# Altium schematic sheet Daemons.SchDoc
size B; DocumentNumber: 1; SheetNumber: 1; SheetTotal: 1
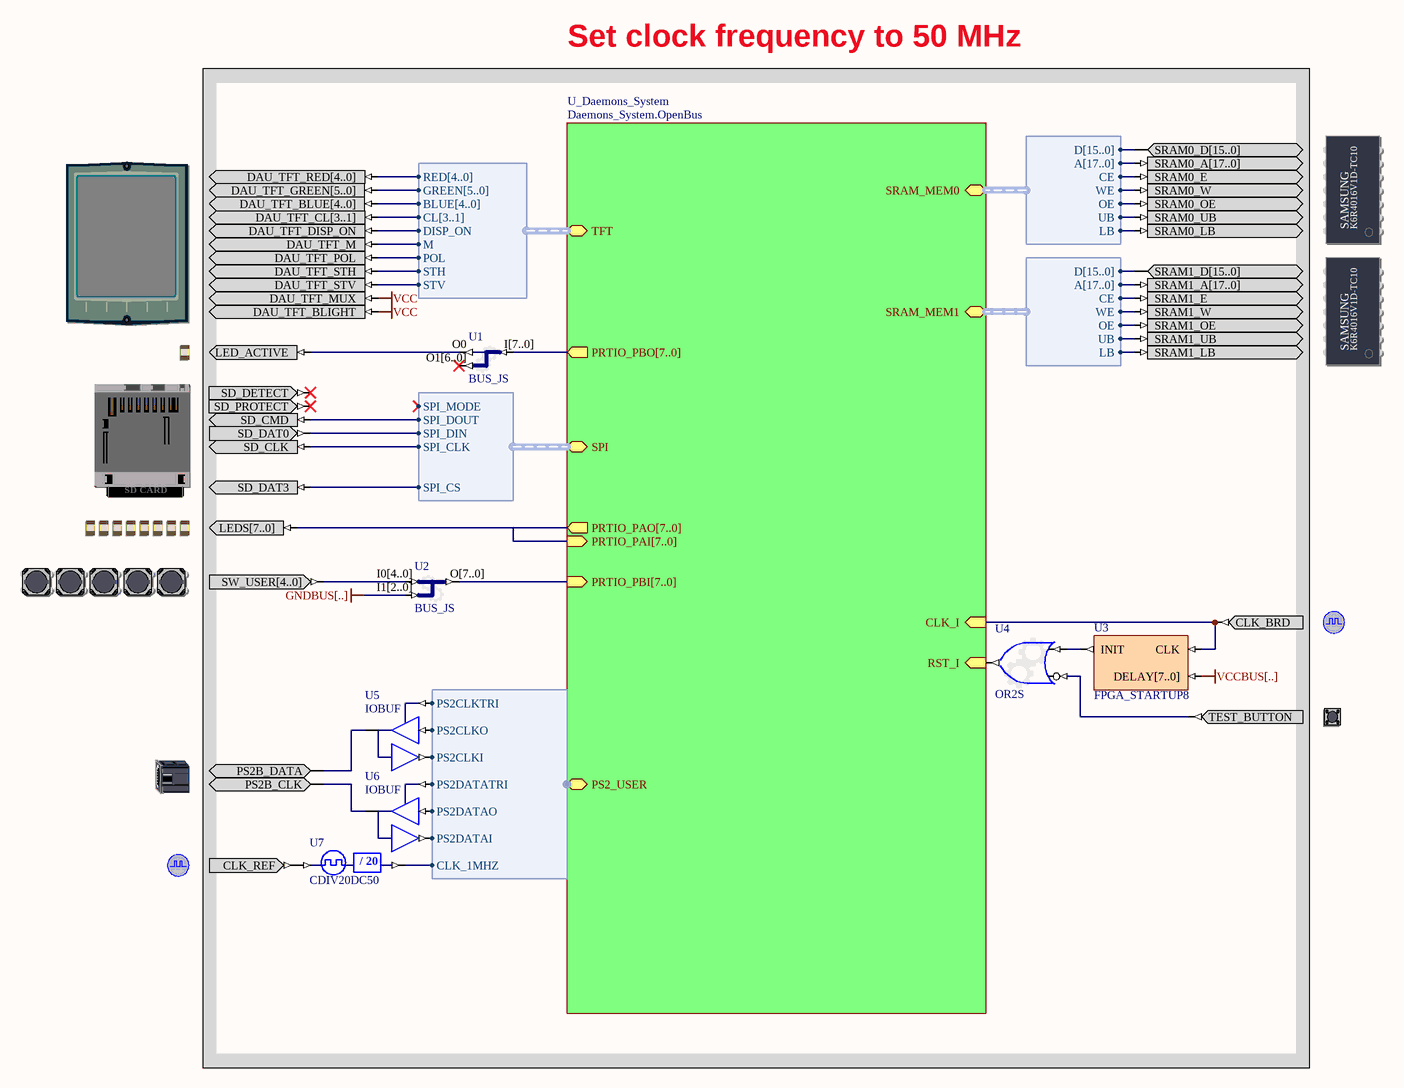
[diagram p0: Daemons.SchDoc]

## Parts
(Parts that share a designator on the sheet are numbered #1, #2 ... from top to bottom, then left to right.)
?#1  SRAM_DAUGHTER0  (value not drawn)
?#2  TFT_LCD  (value not drawn)
?#3  SRAM_DAUGHTER1  (value not drawn)
?#4  LED_ACTIVE  (value not drawn)
?#5  SD_CARD  (value not drawn)
?#6  LED  (value not drawn)
?#7  USER_BUTTONS  (value not drawn)
?#8  CLOCK_BOARD  (value not drawn)
?#9  TEST_BUTTON  (value not drawn)
?#10  PS2B  (value not drawn)
?#11  CLOCK_REFERENCE  (value not drawn)
U1  BUS_JS
U2  BUS_JS
U3  FPGA_STARTUP8
U4  OR2S
U5  IOBUF
U6  IOBUF
U7  CDIV20DC50

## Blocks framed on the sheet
Set clock frequency to 50 MHz: ?#1-?#11 U1-U7

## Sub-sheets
U_Daemons_System = Daemons_System.OpenBus: CLK_I (in), RST_I (in), PRTIO_PAO[7..0] (out), PRTIO_PAI[7..0] (in), PRTIO_PBO[7..0] (out), PRTIO_PBI[7..0] (in), TFT (harness VGA32_TFT), SPI (harness SPI_W), PS2_USER (harness PS2_W), SRAM_MEM0 (harness WB_MEM_CTRL_SRAM16_A18), SRAM_MEM1 (harness WB_MEM_CTRL_SRAM16_A18)

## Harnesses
VGA32_TFT: RED[4..0], GREEN[5..0], BLUE[4..0], CL[3..1], DISP_ON, M, POL, STH, STV
SPI_W: SPI_DOUT, SPI_DIN, SPI_CLK, SPI_MODE, SPI_CS
PS2_W: PS2CLKTRI, PS2CLKO, PS2CLKI, PS2DATATRI, PS2DATAO, PS2DATAI, CLK_1MHZ
WB_MEM_CTRL_SRAM16_A18: D[15..0], A[17..0], CE, WE, OE, UB, LB

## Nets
VCC: ?#2.DAU_TFT_BLIGHT ?#2.DAU_TFT_MUX
VCCBUS[..]: U3.DELAY[7..0]
Net?#1_SRAM0_E: ?#1.SRAM0_E ; sheet U_Daemons_System/SRAM_MEM0.CE
Net?#1_SRAM0_LB: ?#1.SRAM0_LB ; sheet U_Daemons_System/SRAM_MEM0.LB
Net?#1_SRAM0_OE: ?#1.SRAM0_OE ; sheet U_Daemons_System/SRAM_MEM0.OE
Net?#1_SRAM0_UB: ?#1.SRAM0_UB ; sheet U_Daemons_System/SRAM_MEM0.UB
Net?#1_SRAM0_W: ?#1.SRAM0_W ; sheet U_Daemons_System/SRAM_MEM0.WE
Net?#2_DAU_TFT_DISP_ON: ?#2.DAU_TFT_DISP_ON ; sheet U_Daemons_System/TFT.DISP_ON
Net?#2_DAU_TFT_M: ?#2.DAU_TFT_M ; sheet U_Daemons_System/TFT.M
Net?#2_DAU_TFT_POL: ?#2.DAU_TFT_POL ; sheet U_Daemons_System/TFT.POL
Net?#2_DAU_TFT_STH: ?#2.DAU_TFT_STH ; sheet U_Daemons_System/TFT.STH
Net?#2_DAU_TFT_STV: ?#2.DAU_TFT_STV ; sheet U_Daemons_System/TFT.STV
Net?#3_SRAM1_E: ?#3.SRAM1_E ; sheet U_Daemons_System/SRAM_MEM1.CE
Net?#3_SRAM1_LB: ?#3.SRAM1_LB ; sheet U_Daemons_System/SRAM_MEM1.LB
Net?#3_SRAM1_OE: ?#3.SRAM1_OE ; sheet U_Daemons_System/SRAM_MEM1.OE
Net?#3_SRAM1_UB: ?#3.SRAM1_UB ; sheet U_Daemons_System/SRAM_MEM1.UB
Net?#3_SRAM1_W: ?#3.SRAM1_W ; sheet U_Daemons_System/SRAM_MEM1.WE
Net?#4_LED_ACTIVE: ?#4.LED_ACTIVE U1.O0
Net?#5_SD_CLK: ?#5.SD_CLK ; sheet U_Daemons_System/SPI.SPI_CLK
Net?#5_SD_CMD: ?#5.SD_CMD ; sheet U_Daemons_System/SPI.SPI_DOUT
Net?#5_SD_DAT0: ?#5.SD_DAT0 ; sheet U_Daemons_System/SPI.SPI_DIN
Net?#5_SD_DAT3: ?#5.SD_DAT3 ; sheet U_Daemons_System/SPI.SPI_CS
Net?#8_CLK_BRD: ?#8.CLK_BRD U3.CLK ; sheet U_Daemons_System/CLK_I
Net?#9_TEST_BUTTON: ?#9.TEST_BUTTON U4.I1
Net?#10_PS2B_CLK: ?#10.PS2B_CLK U6.IO
Net?#10_PS2B_DATA: ?#10.PS2B_DATA U5.IO
Net?#11_CLK_REF: ?#11.CLK_REF U7.CLKIN
NetU3_INIT: U3.INIT U4.I0
NetU4_O: U4.O ; sheet U_Daemons_System/RST_I
NetU5_I: U5.I ; sheet U_Daemons_System/PS2_USER.PS2CLKO
NetU5_O: U5.O ; sheet U_Daemons_System/PS2_USER.PS2CLKI
NetU5_T: U5.T ; sheet U_Daemons_System/PS2_USER.PS2CLKTRI
NetU6_I: U6.I ; sheet U_Daemons_System/PS2_USER.PS2DATAO
NetU6_O: U6.O ; sheet U_Daemons_System/PS2_USER.PS2DATAI
NetU6_T: U6.T ; sheet U_Daemons_System/PS2_USER.PS2DATATRI
NetU7_CLKDV: U7.CLKDV ; sheet U_Daemons_System/PS2_USER.CLK_1MHZ

Not connected (* = marked no-connect by the designer): ?#1 SRAM0_A[17..0] SRAM0_D[15..0]; ?#2 DAU_TFT_BLUE[4..0] DAU_TFT_CL[3..1] DAU_TFT_GREEN[5..0] DAU_TFT_RED[4..0]; ?#3 SRAM1_A[17..0] SRAM1_D[15..0]; ?#5 SD_DETECT* SD_PROTECT*; ?#6 LEDS[7..0]; ?#7 SW_USER[4..0]; U1 I[7..0] O1[6..0]*; U2 I0[4..0] I1[2..0] O[7..0]

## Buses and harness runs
bus sheet U_Daemons_System/PRTIO_PAI[7..0] = sheet U_Daemons_System/PRTIO_PAO[7..0]

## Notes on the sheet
- Labels drawn without touching a wire or pin: GNDBUS[..]

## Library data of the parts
?#1 = SRAM_DAUGHTER0: Free Static RAM - Daughterboard; PortComponent: True
?#2 = TFT_LCD: TFT LCD Panel; PortComponent: True
?#3 = SRAM_DAUGHTER1: Free Static RAM - Daughterboard; PortComponent: True
?#4 = LED_ACTIVE: LED; PortComponent: True
?#5 = SD_CARD: Secure Digital Card Socket; PortComponent: True
?#6 = LED: Bank of eight Red LEDs; PortComponent: True
?#7 = USER_BUTTONS: Generic User Buttons; PortComponent: True
?#8 = CLOCK_BOARD: Global System Clock Supply; PortComponent: True
?#9 = TEST_BUTTON: Test / Reset Button; PortComponent: True
?#10 = PS2B: Key Board PS2 Connector; PortComponent: True
?#11 = CLOCK_REFERENCE: Global System Clock Reference Supply; PortComponent: True
U1 = BUS_JS: Configurable Bus Joiner/Splitter; ConfiguratorName: GENERIC_BUS_JS; ConfigurationParameters: {}Version[1.0]{}SplitterJoinerType[Splitter]{}SignalCount[2]{}SignalWidth0[1]{}SignalWidth1[7]{}
U2 = BUS_JS: Configurable Bus Joiner/Splitter; ConfiguratorName: GENERIC_BUS_JS; ConfigurationParameters: {}Version[1.0]{}SplitterJoinerType[Joiner]{}SignalCount[2]{}SignalWidth0[5]{}SignalWidth1[3]{}
U3 = FPGA_STARTUP8: FPGA Startup With 8 Bit Delay
U4 = GATE: Configurable Generic Gate; ConfiguratorName: GENERIC_GATE; ConfigurationParameters: {}Version[1.0]{}GateKind[OR]{}BusInput[False]{}GateInputType[Bit]{}GateOutputOption[Normal]{}BusWidth[8]{}RegisterOutputs[False]{}NegativeClockEdge[False]{}InputCount[2]{}InputInvert0[False]{}InputInvert1[True]{}
U5 U6 = IOBUF: Input/Output Buffer; Enable: Low; Control: Common Control T; ArchiveName: GENERIC; VHDLIB_SIM: GENERIC_LIB
U7 = CDIV20DC50: Clock Divider by 20 with 50% Duty Cycle Output; DivisorRate: 20; DutyCycle: 50; ArchiveName: GENERIC; VHDLIB_SIM: GENERIC_LIB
